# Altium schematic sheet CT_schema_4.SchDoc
size 445 x 328 mm
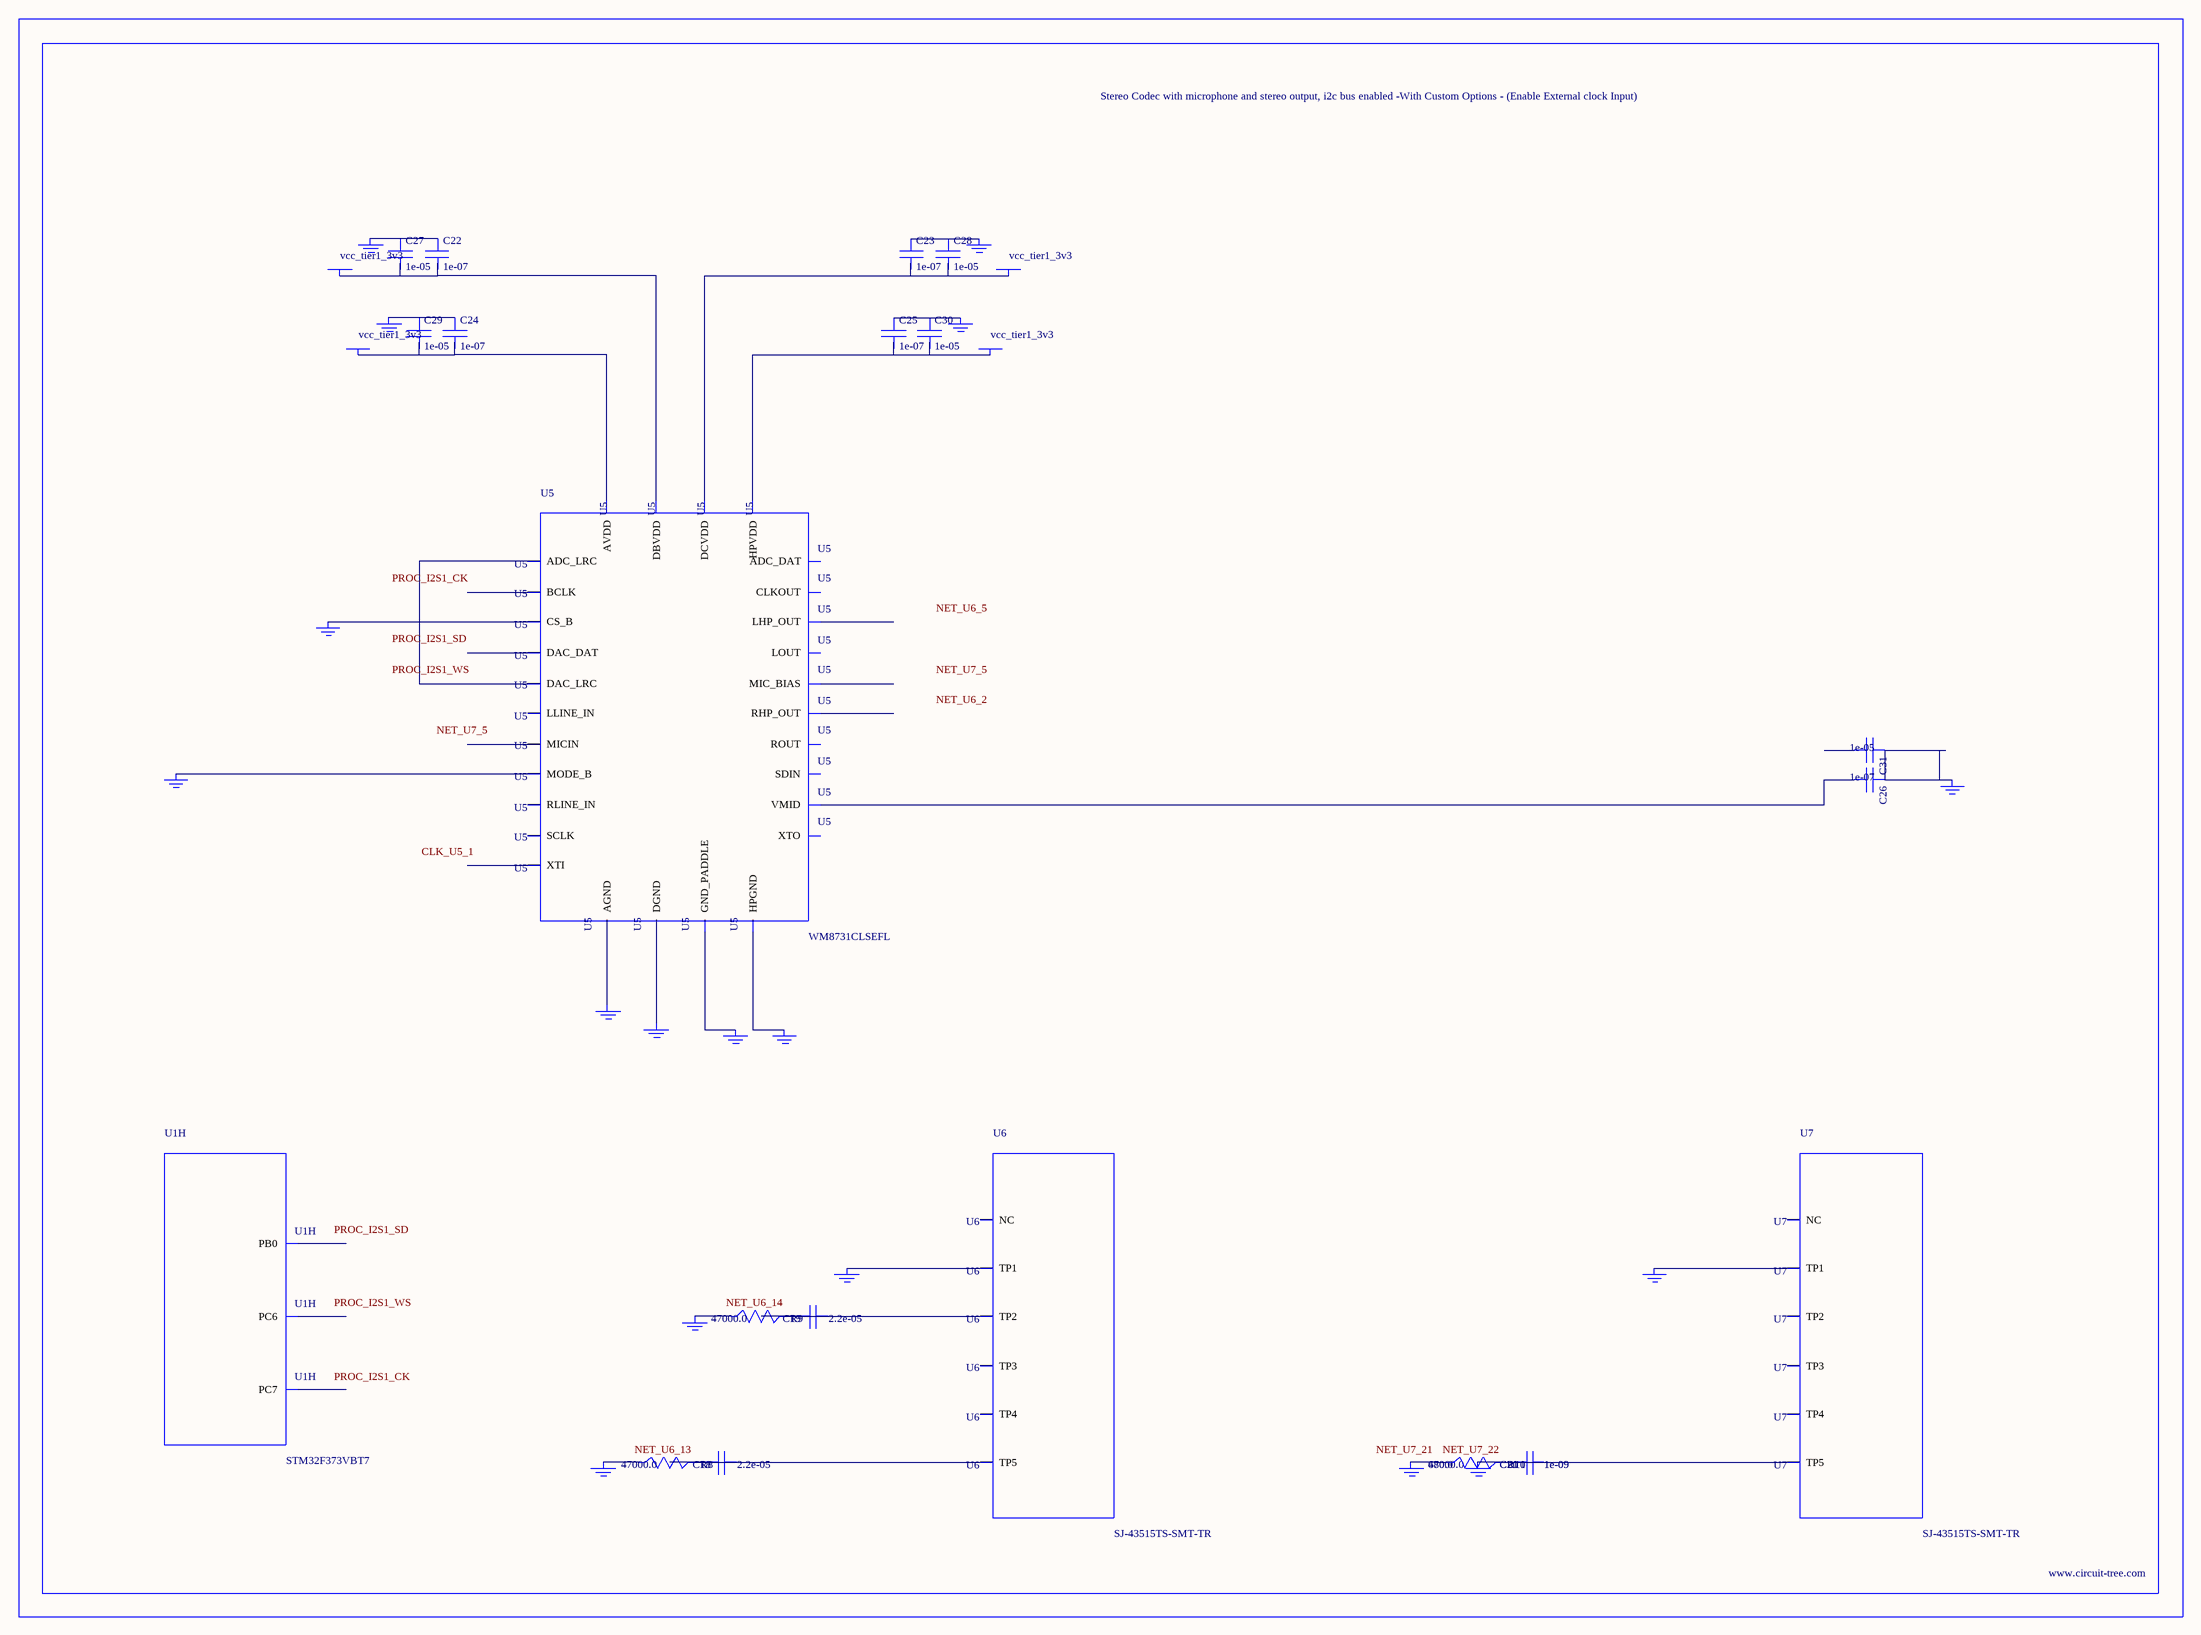
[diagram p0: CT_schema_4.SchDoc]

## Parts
BORDER3  (no value)
C18  2.2e-05  [C1210]
C19  2.2e-05  [C1210]
C20  1e-09  [C0402]
C21  1e-09  [C0402]
C22  1e-07  [C0402]
C23  1e-07  [C0402]
C24  1e-07  [C0402]
C25  1e-07  [C0402]
C26  1e-07  [C0402]
C27  1e-05  [C0805]
C28  1e-05  [C0805]
C29  1e-05  [C0805]
C30  1e-05  [C0805]
C31  1e-05  [C0805]
GND_INSTANCE_3_0  (no value)
GND_INSTANCE_3_1  (no value)
GND_INSTANCE_3_2  (no value)
GND_INSTANCE_3_3  (no value)
GND_INSTANCE_3_4  (no value)
GND_INSTANCE_3_5  (no value)
GND_INSTANCE_3_6  (no value)
GND_INSTANCE_3_7  (no value)
GND_INSTANCE_3_8  (no value)
GND_INSTANCE_3_9  (no value)
GND_INSTANCE_3_10  (no value)
GND_INSTANCE_3_11  (no value)
GND_INSTANCE_3_12  (no value)
GND_INSTANCE_3_13  (no value)
GND_INSTANCE_3_14  (no value)
GND_INSTANCE_3_15  (no value)
GND_INSTANCE_3_16  (no value)
POWER_INSTANCE_3_0  vcc_tier1_3v3
POWER_INSTANCE_3_1  vcc_tier1_3v3
POWER_INSTANCE_3_2  vcc_tier1_3v3
POWER_INSTANCE_3_3  vcc_tier1_3v3
R8  47000.0  [R0603]
R9  47000.0  [R0603]
R10  47000.0  [R0603]
R11  680.0  [R0603]
U1  STM32F373VBT7  [LQFP100]  (part H of 9)
U5  WM8731CLSEFL  [QFN-28]
U6  SJ-43515TS-SMT-TR  [SJ-43515TS-SMT-TR]
U7  SJ-43515TS-SMT-TR  [SJ-43515TS-SMT-TR]

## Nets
NetC18_1: C18.1 C18.2 R8.2 U6.5(TP5)
NetC19_1: C19.1 C19.2 R9.2 U6.2(TP2)
NetC20_1: C20.1 C20.2 C21.1 C21.2 GND_INSTANCE_3_16.0(GND) R10.2 R11.2 U7.5(TP5)
NetC22_1: C22.1 C27.1 GND_INSTANCE_3_1.0(GND)
NetC22_2: C22.2 C27.2 POWER_INSTANCE_3_1.0(PWR) U5.5(DBVDD)
NetC23_1: C23.1 C28.1 GND_INSTANCE_3_0.0(GND)
NetC23_2: C23.2 C28.2 POWER_INSTANCE_3_0.0(PWR) U5.3(DCVDD)
NetC24_1: C24.1 C29.1 GND_INSTANCE_3_4.0(GND)
NetC24_2: C24.2 C29.2 POWER_INSTANCE_3_3.0(PWR) U5.18(AVDD)
NetC25_1: C25.1 C30.1 GND_INSTANCE_3_2.0(GND)
NetC25_2: C25.2 C30.2 POWER_INSTANCE_3_2.0(PWR) U5.12(HPVDD)
NetC26_1: C26.1 C31.1 GND_INSTANCE_3_5.0(GND)
NetC26_2: C26.2 U5.20(VMID)
NetGND_INSTANCE_3_3_0: GND_INSTANCE_3_3.0(GND) U5.15(HPGND)
NetGND_INSTANCE_3_6_0: GND_INSTANCE_3_6.0(GND) U5.25(MODE_B)
NetGND_INSTANCE_3_7_0: GND_INSTANCE_3_7.0(GND) U5.26(CS_B)
NetGND_INSTANCE_3_8_0: GND_INSTANCE_3_8.0(GND) U5.29(GND_PADDLE)
NetGND_INSTANCE_3_9_0: GND_INSTANCE_3_9.0(GND) U5.4(DGND)
NetGND_INSTANCE_3_10_0: GND_INSTANCE_3_10.0(GND) U5.19(AGND)
NetGND_INSTANCE_3_11_0: GND_INSTANCE_3_11.0(GND) U6.1(TP1)
NetGND_INSTANCE_3_12_0: GND_INSTANCE_3_12.0(GND) R9.1
NetGND_INSTANCE_3_13_0: GND_INSTANCE_3_13.0(GND) R8.1
NetGND_INSTANCE_3_14_0: GND_INSTANCE_3_14.0(GND) U7.1(TP1)
NetGND_INSTANCE_3_15_0: GND_INSTANCE_3_15.0(GND) R10.1 R11.1
NetU5_9: U5.9(DAC_LRC) U5.11(ADC_LRC)

Not connected (* = marked no-connect by the designer): C31 2; U1 35(PB0) 63(PC6) 64(PC7); U5 1(XTI) 2(XTO) 6(CLKOUT) 7(BCLK) 8(DAC_DAT) 10(ADC_DAT) 13(LHP_OUT) 14(RHP_OUT) 16(LOUT) 17(ROUT) 21(MIC_BIAS) 22(MICIN) 23(RLINE_IN) 24(LLINE_IN) 27(SDIN) 28(SCLK); U6 3(TP3) 4(TP4) 6(NC); U7 2(TP2) 3(TP3) 4(TP4) 6(NC)

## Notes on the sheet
- Labels drawn without touching a wire or pin: CLK_U5_1, NET_U6_2, NET_U6_5, NET_U6_13, NET_U6_14, NET_U7_5, NET_U7_21, NET_U7_22, PROC_I2S1_CK, PROC_I2S1_SD, PROC_I2S1_WS

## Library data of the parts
BORDER3 = BORDER_PAGE3
C18 C19 = C1210C224K5RACTU
C20 C21 = C0402C102K3RAC
C22-C26 = C0402C104K3RACTU
C27-C31 = C0805C106K8RACTU
GND_INSTANCE_3_0-GND_INSTANCE_3_16 = GND
POWER_INSTANCE_3_0-POWER_INSTANCE_3_3 = PWR
R8-R10 = RC0603JR-0747KL
R11 = RC0603JR-07680RL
